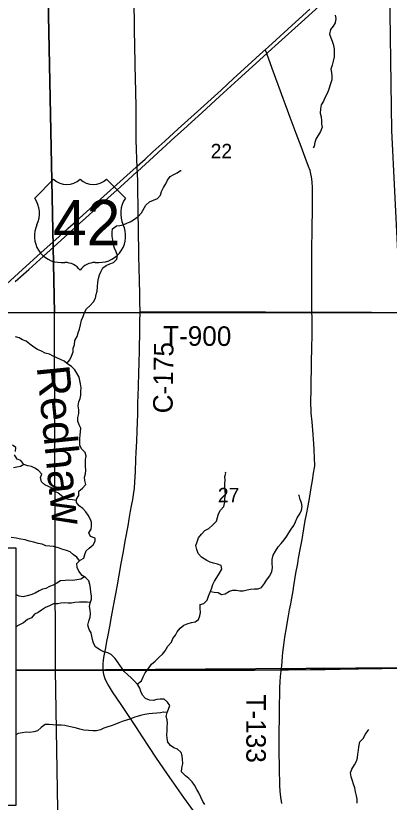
# Model space of a CAD drawing. Extents: x 0 to 34, y 0 to 22.
# Drawn here: x 5.987 to 7.072, y 17.462 to 19.744 of the extents above; entities that cross this region are included whole.
import ezdxf

# ---------------------------------------------------------------- set-up
doc = ezdxf.new("R2010")
doc.units = 0
for name, color, linetype in [('Default', 7, 'Continuous'), ('GM_X_County_Road', 7, 'Continuous'), ('GM_X_County_Road_Text', 7, 'Continuous'), ('GM_X_Minor_River', 7, 'Continuous'), ('GM_X_Minor_River_Text', 7, 'Continuous'), ('GM_X_Section', 7, 'Continuous'), ('GM_X_Section_Text', 7, 'Continuous'), ('GM_X_State_Route', 7, 'Continuous'), ('GM_X_Township_Road', 7, 'Continuous'), ('GM_X_Township_Road_Text', 7, 'Continuous'), ('GM_X_US_Location', 7, 'Continuous'), ('GM_X_US_Route', 7, 'Continuous'), ('GM_X_US_Shield', 7, 'Continuous'), ('SH_Text', 7, 'Continuous')]:
    doc.layers.add(name, color=color, linetype=linetype)

msp = doc.modelspace()

# ---------------------------------------------------------------- linework, layer by layer
at = {"layer": 'Default'}
msp.add_lwpolyline([(4.0336, 18.2003), (5.9872, 18.2003), (5.9872, 17.4527), (4.0336, 17.4527)], close=True, dxfattribs=at)
at = {"layer": 'GM_X_County_Road'}
for points in [[(6.3403, 19.2924), (6.3401, 19.2991), (6.3397, 19.3075), (6.339, 19.3239), (6.3378, 19.3605), (6.3372, 19.3796), (6.3366, 19.4139), (6.3365, 19.4358), (6.3365, 19.4792), (6.3359, 19.5239), (6.334, 19.5995), (6.3332, 19.6622), (6.3324, 19.6969), (6.3318, 19.7398), (6.3303, 19.7815), (6.3297, 19.8065), (6.329, 19.8322), (6.3289, 19.8539), (6.329, 19.8744), (6.3288, 19.8879)], [(6.348, 18.8852), (6.348, 18.8893), (6.3479, 18.911), (6.3473, 18.942), (6.3468, 18.97), (6.3454, 19.0181), (6.3447, 19.0397), (6.3443, 19.0643), (6.3438, 19.1129), (6.3435, 19.1375), (6.343, 19.162), (6.3426, 19.1774), (6.3426, 19.1936), (6.3418, 19.2339), (6.3413, 19.2587), (6.3403, 19.2924)], [(6.2412, 17.8453), (6.2408, 17.8488), (6.2405, 17.8547), (6.2409, 17.8638), (6.2418, 17.873), (6.2432, 17.8822), (6.2484, 17.9097), (6.252, 17.928), (6.2554, 17.9463), (6.261, 17.9769), (6.2633, 17.9891), (6.2672, 18.0109), (6.2728, 18.0413), (6.2814, 18.087), (6.2876, 18.121), (6.2937, 18.1548), (6.2992, 18.1844), (6.3061, 18.2242), (6.3132, 18.2642), (6.3166, 18.2834), (6.3206, 18.307), (6.3236, 18.3223), (6.3268, 18.3406), (6.3303, 18.3611), (6.3318, 18.3733), (6.3332, 18.3918), (6.3345, 18.4206), (6.336, 18.4578), (6.3366, 18.4766), (6.3383, 18.51), (6.3397, 18.5389), (6.3405, 18.5653), (6.3412, 18.5883), (6.342, 18.6192), (6.3426, 18.6444), (6.3433, 18.6658), (6.3439, 18.6818), (6.3443, 18.6953), (6.3449, 18.7099), (6.3457, 18.734), (6.346, 18.7464), (6.3463, 18.7619), (6.3465, 18.7836), (6.3473, 18.8209), (6.3478, 18.8551), (6.348, 18.8852)], [(6.5035, 17.4366), (6.4752, 17.4757), (6.4343, 17.5338), (6.4169, 17.5594), (6.3942, 17.5932), (6.3757, 17.621), (6.3555, 17.6516), (6.3381, 17.6784), (6.3143, 17.7137), (6.2932, 17.7455), (6.2684, 17.7826), (6.2592, 17.7972), (6.2545, 17.8048), (6.25, 17.8133), (6.2472, 17.8199), (6.2449, 17.8263), (6.2432, 17.8322), (6.2419, 17.8385), (6.2412, 17.8453)]]:
    msp.add_lwpolyline(points, dxfattribs=at)
at = {"layer": 'GM_X_Minor_River'}
for points in [[(6.9151, 19.7459), (6.9169, 19.7357), (6.9149, 19.7239), (6.9095, 19.7141), (6.9015, 19.7043), (6.8991, 19.6903), (6.9021, 19.6804), (6.9061, 19.6702), (6.9102, 19.6591), (6.9124, 19.6458), (6.9123, 19.6344), (6.9126, 19.6249), (6.9094, 19.6125), (6.9059, 19.6007), (6.9028, 19.5894), (6.9046, 19.5799), (6.9053, 19.5685), (6.9052, 19.5579), (6.9009, 19.5435), (6.897, 19.531), (6.8924, 19.5201), (6.8854, 19.5061), (6.8816, 19.4963), (6.8746, 19.4857), (6.8727, 19.4743), (6.8718, 19.4611), (6.874, 19.4508), (6.8754, 19.4394), (6.8753, 19.4299), (6.8771, 19.4204), (6.8721, 19.4083), (6.8667, 19.3985), (6.8598, 19.3876), (6.8559, 19.3759), (6.8536, 19.366), (6.8512, 19.3604)], [(6.1355, 18.7351), (6.1443, 18.7458), (6.149, 18.7568), (6.1536, 18.7685), (6.1541, 18.7791), (6.1572, 18.7897), (6.1588, 18.8014), (6.165, 18.8135), (6.1681, 18.8241), (6.172, 18.8347), (6.1751, 18.8472), (6.1782, 18.8604), (6.1825, 18.8714), (6.1864, 18.8831), (6.1922, 18.8933), (6.2017, 18.9027), (6.2124, 18.9144), (6.2185, 18.9242), (6.2209, 18.9355), (6.2233, 18.9454), (6.2249, 18.9571), (6.2258, 18.9715), (6.2277, 18.9817), (6.2305, 18.992), (6.2351, 19.0025), (6.2401, 19.0124), (6.25, 19.0195), (6.2607, 19.0243), (6.2706, 19.0284), (6.2805, 19.0381), (6.2825, 19.0487), (6.2784, 19.0594), (6.2739, 19.0693), (6.2703, 19.0819), (6.2688, 19.0929), (6.2674, 19.105), (6.2671, 19.116), (6.268, 19.1255), (6.2794, 19.1345), (6.2896, 19.1355), (6.2995, 19.1377), (6.3094, 19.1418), (6.3197, 19.1466), (6.3295, 19.1522), (6.3425, 19.162), (6.3521, 19.1721), (6.3651, 19.1948), (6.3758, 19.2041), (6.3868, 19.209), (6.3986, 19.2142), (6.4078, 19.2239), (6.4109, 19.2338), (6.4159, 19.2459), (6.4228, 19.2568), (6.4282, 19.267), (6.4355, 19.2775), (6.4462, 19.2831), (6.4564, 19.2883), (6.4659, 19.2947), (6.4675, 19.2947)], [(6.2541, 17.8956), (6.2431, 17.8988), (6.2311, 17.9046), (6.219, 17.9134), (6.2127, 17.9233), (6.2097, 17.9344), (6.2079, 17.9439), (6.2061, 17.9537), (6.2001, 17.9633), (6.1968, 17.9762), (6.1992, 17.9876), (6.2027, 17.9986), (6.2039, 18.0095), (6.2033, 18.019), (6.2015, 18.0301), (6.2034, 18.0399), (6.2066, 18.0509), (6.2067, 18.0607), (6.2052, 18.0718), (6.2042, 18.0828), (6.202, 18.0934), (6.1991, 18.1044), (6.1897, 18.114), (6.1795, 18.1202), (6.1698, 18.1324), (6.1653, 18.1431), (6.1647, 18.1545), (6.1742, 18.1646), (6.1845, 18.1699), (6.188, 18.1804), (6.1911, 18.191), (6.2006, 18.1989), (6.2117, 18.2087), (6.2178, 18.2192), (6.2172, 18.2287), (6.2043, 18.2326), (6.1995, 18.2441), (6.2056, 18.2543), (6.2072, 18.2645), (6.207, 18.2744), (6.2033, 18.2846), (6.1969, 18.2949), (6.1905, 18.3045), (6.1819, 18.3141), (6.1714, 18.3218), (6.1639, 18.3313), (6.1632, 18.3412), (6.1705, 18.3517), (6.1706, 18.3643), (6.1809, 18.3729), (6.1901, 18.3838), (6.1879, 18.3956), (6.1869, 18.4051), (6.19, 18.4153), (6.1904, 18.4251), (6.1898, 18.4365), (6.1899, 18.4464), (6.1892, 18.4563), (6.1915, 18.4665), (6.1886, 18.4764), (6.1792, 18.4867), (6.1733, 18.4974), (6.1734, 18.5179), (6.1739, 18.5274), (6.1747, 18.538), (6.1756, 18.5475), (6.1715, 18.557), (6.1674, 18.5676), (6.1671, 18.5787), (6.1706, 18.59), (6.1703, 18.6002), (6.1678, 18.612), (6.1705, 18.6234), (6.174, 18.6336), (6.176, 18.6434), (6.1765, 18.6544), (6.1766, 18.6643), (6.1752, 18.6765), (6.1733, 18.686), (6.1712, 18.6955), (6.1644, 18.7069), (6.1588, 18.7168), (6.1491, 18.726), (6.1378, 18.7334), (6.1272, 18.7414), (6.1174, 18.7465), (6.1065, 18.7511), (6.0959, 18.7561), (6.085, 18.7619), (6.0725, 18.7655), (6.0616, 18.7705), (6.0499, 18.7759), (6.0397, 18.7825), (6.0277, 18.791), (6.0176, 18.8002), (6.0066, 18.8041), (5.9964, 18.8099), (5.9858, 18.8122)], [(5.9857, 18.4795), (5.9873, 18.4909), (5.9771, 18.4978)], [(6.1635, 18.3373), (6.1522, 18.339), (6.1409, 18.3403), (6.1307, 18.3434), (6.1194, 18.3515), (6.1096, 18.3595), (6.0998, 18.3634), (6.0923, 18.373), (6.0821, 18.3784), (6.0719, 18.3827), (6.0622, 18.3915), (6.0592, 18.404), (6.0627, 18.4139), (6.053, 18.4242), (6.0428, 18.4315), (6.033, 18.4362), (6.0224, 18.4378), (6.0107, 18.4417), (6.0013, 18.4535), (5.9908, 18.4574), (5.9829, 18.4697)], [(6.0107, 18.4417), (6.0004, 18.4361), (5.9902, 18.4343), (5.9807, 18.4321)], [(6.34, 17.8042), (6.3519, 17.8146), (6.3573, 17.8255), (6.363, 17.8373), (6.3722, 17.8504), (6.3818, 17.8625), (6.3921, 17.8711), (6.4032, 17.8828), (6.4135, 17.8914), (6.4211, 17.9016), (6.4292, 17.9144), (6.4391, 17.9264), (6.4434, 17.937), (6.4507, 17.9468), (6.4564, 17.9566), (6.4649, 17.9675), (6.4755, 17.9762), (6.485, 17.9799), (6.4976, 17.9835), (6.5078, 17.9853), (6.5177, 17.9925), (6.5216, 18.0027), (6.5239, 18.0125), (6.5225, 18.0243), (6.523, 18.0353), (6.5333, 18.039), (6.5432, 18.048), (6.5471, 18.0601), (6.5556, 18.0813), (6.5598, 18.0934), (6.5641, 18.1036), (6.571, 18.1141), (6.5791, 18.1262), (6.5856, 18.1379), (6.5834, 18.1485), (6.5732, 18.1524), (6.5619, 18.1559), (6.5521, 18.1583), (6.5423, 18.1633), (6.5264, 18.1734), (6.5167, 18.1837), (6.513, 18.1951), (6.5104, 18.2065), (6.5139, 18.2175), (6.5182, 18.2296), (6.5262, 18.2394), (6.5366, 18.2507), (6.5484, 18.2562), (6.559, 18.266), (6.5705, 18.278), (6.5732, 18.2882), (6.576, 18.2988), (6.5818, 18.3094), (6.5917, 18.3203), (6.5941, 18.3324), (6.5942, 18.3438), (6.5965, 18.3537), (6.5959, 18.3658), (6.5948, 18.3757), (6.5949, 18.3863), (6.5954, 18.3965), (6.5947, 18.4068), (6.5974, 18.4166), (6.5963, 18.4193)], [(6.5526, 18.0739), (6.5634, 18.0717), (6.5748, 18.0704), (6.5846, 18.0647), (6.5956, 18.0664), (6.6082, 18.0743), (6.618, 18.0776), (6.6279, 18.0775), (6.6381, 18.0759), (6.6479, 18.0754), (6.6589, 18.0784), (6.6692, 18.0805), (6.6798, 18.0808), (6.6911, 18.0815), (6.7006, 18.0852), (6.7098, 18.0964), (6.7156, 18.1063), (6.7255, 18.1191), (6.7306, 18.1312), (6.7329, 18.1421), (6.7319, 18.1554), (6.732, 18.166), (6.7351, 18.1785), (6.7413, 18.1906), (6.7497, 18.2027), (6.7585, 18.2128), (6.7666, 18.223), (6.7742, 18.2339), (6.7807, 18.2437), (6.7877, 18.2543), (6.7949, 18.2652), (6.7996, 18.2754), (6.8042, 18.2871), (6.8123, 18.2984), (6.8173, 18.309), (6.8193, 18.3204), (6.8171, 18.331), (6.8138, 18.3409), (6.8101, 18.3523), (6.809, 18.3543)], [(6.1723, 18.1626), (6.1648, 18.1731), (6.155, 18.18), (6.1449, 18.1881), (6.1343, 18.1923), (6.1211, 18.1963), (6.1109, 18.1998), (6.0969, 18.2045), (6.0863, 18.2053), (6.0742, 18.2062), (6.0637, 18.2105), (6.0516, 18.2129), (6.0391, 18.2168), (6.0262, 18.22), (6.0145, 18.2235), (6.0017, 18.2255), (5.9877, 18.2287), (5.9737, 18.2303)], [(6.1866, 18.1159), (6.1764, 18.1092), (6.1646, 18.1071), (6.1529, 18.1057), (6.1412, 18.1062), (6.1305, 18.1055), (6.1173, 18.1049), (6.1066, 18.0981), (6.0956, 18.0918), (6.0853, 18.0881), (6.0747, 18.0821), (6.0648, 18.08), (6.0549, 18.0751), (6.0431, 18.0688), (6.031, 18.064), (6.02, 18.0607), (6.0082, 18.0581), (5.9972, 18.0601), (5.9868, 18.0646)], [(6.2039, 18.0415), (6.194, 18.043), (6.1815, 18.0428), (6.1717, 18.0425), (6.1588, 18.0411), (6.1493, 18.0393), (6.1395, 18.0398), (6.1296, 18.041), (6.1182, 18.0392), (6.1088, 18.0374), (6.097, 18.0379), (6.0852, 18.0319), (6.0731, 18.0275), (6.062, 18.0197), (6.0518, 18.0129), (6.0415, 18.0073), (6.0331, 17.9972), (6.0213, 17.9924), (6.0091, 17.9826), (5.9961, 17.9755), (5.9868, 17.9708)], [(6.5362, 17.455), (6.531, 17.4645), (6.5251, 17.4763), (6.5191, 17.4889), (6.5131, 17.4988), (6.5061, 17.5114), (6.4993, 17.521), (6.4903, 17.5306), (6.4798, 17.5386), (6.4685, 17.5505), (6.4694, 17.5607), (6.4729, 17.574), (6.4715, 17.5861), (6.4708, 17.5968), (6.4675, 17.6063), (6.457, 17.6159), (6.4464, 17.6194), (6.4362, 17.6263), (6.4284, 17.6367), (6.4273, 17.6465), (6.4259, 17.6583), (6.4271, 17.6685), (6.4272, 17.6811), (6.4281, 17.6905), (6.4266, 17.7008), (6.4237, 17.7107), (6.4268, 17.7224), (6.4311, 17.7322), (6.4346, 17.7428), (6.4282, 17.7524), (6.4181, 17.7612), (6.4063, 17.7609), (6.3968, 17.7599), (6.3866, 17.757), (6.3752, 17.7582), (6.3643, 17.7633), (6.3549, 17.7728), (6.3508, 17.7831), (6.3471, 17.7926), (6.3415, 17.8026), (6.3318, 17.8129), (6.3224, 17.8225), (6.3122, 17.8313), (6.3017, 17.8409), (6.2961, 17.8504), (6.2898, 17.86), (6.2827, 17.8695), (6.2759, 17.8791), (6.2639, 17.8902), (6.2541, 17.8956)], [(6.4268, 17.7224), (6.4166, 17.7229), (6.4071, 17.7211), (6.3965, 17.7201), (6.3844, 17.7198), (6.3741, 17.7184), (6.3624, 17.717), (6.3529, 17.7144), (6.3423, 17.7119), (6.3301, 17.7082), (6.318, 17.7034), (6.3085, 17.7), (6.2963, 17.696), (6.2865, 17.6927), (6.2751, 17.6879), (6.2637, 17.6834), (6.2542, 17.6805), (6.2432, 17.6772), (6.2329, 17.6719), (6.2219, 17.669), (6.2105, 17.6695), (6.198, 17.67), (6.1852, 17.6713), (6.1735, 17.6737), (6.1633, 17.6768), (6.1508, 17.6803), (6.141, 17.6816), (6.1296, 17.6843), (6.119, 17.6852), (6.1077, 17.6861), (6.0948, 17.6866), (6.0842, 17.6874), (6.0721, 17.6879), (6.0607, 17.6793), (6.0503, 17.6695), (6.039, 17.6659), (6.0272, 17.6648), (6.0174, 17.6653), (6.0064, 17.6631), (5.9942, 17.6614), (5.9868, 17.6573)], [(6.9786, 17.4594), (6.979, 17.4712), (6.9768, 17.4807), (6.9743, 17.4921), (6.9725, 17.5035), (6.9684, 17.5141), (6.9659, 17.5237), (6.9618, 17.5355), (6.9596, 17.5472), (6.9631, 17.5582), (6.9708, 17.5707), (6.9766, 17.5812), (6.9801, 17.5911), (6.9813, 17.6017), (6.9825, 17.6127), (6.9841, 17.6229), (6.9869, 17.6369), (6.9961, 17.6467), (7.003, 17.6591), (7.0103, 17.6689), (7.0133, 17.6735)]]:
    msp.add_lwpolyline(points, dxfattribs=at)
at = {"layer": 'GM_X_Section'}
for points in [[(6.0796, 19.8902), (6.0998, 18.8817), (5.0689, 18.882), (5.0715, 19.8844)], [(7.0719, 19.8884), (7.0785, 19.4112), (7.105, 18.883), (6.0998, 18.8817), (6.0796, 19.8902)], [(5.9868, 17.8455), (6.1027, 17.8448), (6.0998, 18.8817), (5.0689, 18.882), (5.0723, 18.2003), (5.9868, 18.2003)], [(7.105, 18.883), (7.1203, 17.8521), (6.1027, 17.8448), (6.0998, 18.8817)], [(7.1203, 17.8521), (7.1264, 16.8648), (6.1739, 16.8615), (6.1193, 16.8628), (6.1027, 17.8448)], [(5.0909, 17.4527), (5.1149, 16.8654), (5.1862, 16.8638), (6.1193, 16.8628), (6.1027, 17.8448), (5.9868, 17.8455), (5.9868, 17.4527)]]:
    msp.add_lwpolyline(points, close=True, dxfattribs=at)
at = {"layer": 'GM_X_State_Route'}
msp.add_lwpolyline([(5.9868, 17.8453), (6.0453, 17.8454), (6.0939, 17.8456), (6.1467, 17.8456), (6.184, 17.8456), (6.2253, 17.8451), (6.2412, 17.8453), (6.2938, 17.8454), (6.36, 17.8451), (6.4041, 17.8451), (6.4481, 17.845), (6.5009, 17.8451), (6.5599, 17.8453), (6.6064, 17.8451), (6.6437, 17.8451), (6.681, 17.8451), (6.7585, 17.8461), (6.7797, 17.8464), (6.8437, 17.8468), (6.8863, 17.8473), (6.9292, 17.8483), (6.9833, 17.8491), (7.0515, 17.8505), (7.1089, 17.8514)], dxfattribs=at)
at = {"layer": 'GM_X_Township_Road'}
for points in [[(6.7166, 19.6345), (6.7138, 19.642), (6.7124, 19.6458)], [(6.7499, 19.5436), (6.7324, 19.5915), (6.7166, 19.6345)], [(6.8475, 18.8842), (6.8475, 18.8853), (6.8472, 18.907), (6.8473, 18.9256), (6.8471, 18.9536), (6.847, 18.9784), (6.8472, 19.0032), (6.847, 19.0156), (6.8471, 19.0342), (6.8474, 19.0559), (6.8487, 19.1336), (6.8491, 19.1771), (6.8492, 19.2113), (6.8488, 19.2455), (6.8482, 19.261), (6.8473, 19.2704), (6.8464, 19.2766), (6.8444, 19.2857), (6.842, 19.2948), (6.8378, 19.3066), (6.8283, 19.3327), (6.8164, 19.3645), (6.8019, 19.4025), (6.7845, 19.4486), (6.7728, 19.481), (6.7643, 19.504), (6.7526, 19.5361), (6.7499, 19.5436)], [(6.348, 18.8852), (6.3522, 18.8852), (6.3677, 18.885), (6.3926, 18.8851), (6.4454, 18.8853), (6.4703, 18.8854), (6.5014, 18.8851), (6.5449, 18.8849), (6.576, 18.8848), (6.6662, 18.8847), (6.7128, 18.8845), (6.7626, 18.8844), (6.803, 18.8842), (6.8465, 18.8842), (6.8475, 18.8842)], [(6.7585, 17.8461), (6.7598, 17.8573), (6.7622, 17.8847), (6.7634, 17.8965), (6.7651, 17.9112), (6.7669, 17.9252), (6.769, 17.9405), (6.7734, 17.968), (6.7764, 17.9865), (6.7795, 18.0026), (6.7828, 18.0201), (6.7862, 18.0381), (6.789, 18.0537), (6.7926, 18.075), (6.7951, 18.0903), (6.8012, 18.1264), (6.8063, 18.1543), (6.809, 18.1701), (6.8143, 18.2003), (6.8188, 18.2244), (6.8241, 18.255), (6.8283, 18.2794), (6.8317, 18.2965), (6.8364, 18.3222), (6.8404, 18.3438), (6.8455, 18.3739), (6.8491, 18.3956), (6.8526, 18.4165), (6.8549, 18.432), (6.8557, 18.4392), (6.8555, 18.4605), (6.8543, 18.4857), (6.8535, 18.5022), (6.8511, 18.5287), (6.8478, 18.5658), (6.8456, 18.5906), (6.8449, 18.6029), (6.8448, 18.6153), (6.8457, 18.6681), (6.8466, 18.7329), (6.8476, 18.7863), (6.8483, 18.811), (6.848, 18.8699), (6.8475, 18.8842)], [(6.8475, 18.8842), (6.8838, 18.8841), (6.9211, 18.8841), (6.9709, 18.8841), (6.9989, 18.884), (7.0206, 18.8838), (7.0859, 18.8833)], [(6.7597, 17.4582), (6.7575, 17.4765), (6.7556, 17.4941), (6.7544, 17.5103), (6.7539, 17.5232), (6.7532, 17.5483), (6.7533, 17.5695), (6.7527, 17.6036), (6.7527, 17.6617), (6.7531, 17.7106), (6.7533, 17.7456), (6.7541, 17.7742), (6.7546, 17.795), (6.7555, 17.8115), (6.7567, 17.8268), (6.758, 17.8421), (6.7585, 17.8461)]]:
    msp.add_lwpolyline(points, dxfattribs=at)
at = {"layer": 'GM_X_US_Route'}
for points in [[(5.9852, 18.9729), (6.0248, 19.0079), (6.0569, 19.0373), (6.1286, 19.1017), (6.1493, 19.1204), (6.1724, 19.1413), (6.191, 19.1578), (6.2209, 19.185), (6.2719, 19.2306), (6.302, 19.2575), (6.3387, 19.291), (6.3403, 19.2924), (6.3757, 19.3243), (6.4491, 19.3915), (6.4744, 19.4145), (6.4976, 19.4352), (6.5273, 19.4626), (6.5803, 19.5105), (6.6331, 19.5587), (6.7166, 19.6345), (6.7206, 19.6381), (6.7505, 19.6653), (6.8174, 19.7258), (6.983, 19.8762)], [(5.9141, 18.9251), (5.9952, 18.9975), (6.0598, 19.0558), (6.113, 19.1035), (6.1383, 19.1265), (6.1613, 19.1474), (6.2239, 19.2034), (6.3095, 19.2802), (6.3371, 19.3052), (6.3397, 19.3075), (6.3625, 19.3281), (6.3855, 19.349), (6.4199, 19.3804), (6.4591, 19.4159), (6.5052, 19.4577), (6.5835, 19.5286), (6.6201, 19.5622), (6.6616, 19.5998), (6.6961, 19.6312), (6.7124, 19.6458), (6.7215, 19.654), (6.7998, 19.725), (6.8411, 19.7628)]]:
    msp.add_lwpolyline(points, dxfattribs=at)
at = {"layer": 'GM_X_US_Shield'}
for p, q in [((6.0969, 19.2699), (6.0419, 19.2149)), ((6.3056, 19.2149), (6.2507, 19.2699)), ((6.1188, 19.0282), (6.1298, 19.0282)), ((6.2177, 19.0282), (6.2287, 19.0282))]:
    msp.add_line(p, q, dxfattribs=at)
for centre, radius, start, end in [((6.1353, 19.3091), 0.0549, 225.573, 314.427), ((6.2122, 19.3091), 0.0549, 225.573, 314.427), ((5.9789, 19.1708), 0.0769, 334.5471, 35.0009), ((6.3686, 19.1708), 0.0769, 144.9991, 205.4529), ((6.118, 19.1051), 0.0769, 154.8319, 270.6383), ((6.2295, 19.1051), 0.0769, 269.3617, 25.1681), ((6.1298, 18.9732), 0.0549, 36.8699, 90), ((6.2177, 18.9732), 0.0549, 90, 143.1301)]:
    msp.add_arc(centre, radius, start, end, dxfattribs=at)
at = {"layer": 'SH_Text'}
msp.add_lwpolyline([(4.0336, 18.2003), (5.9868, 18.2003), (5.9868, 17.4527), (4.0336, 17.4527)], close=True, dxfattribs=at)

# ---------------------------------------------------------------- texts
at = {"layer": 'GM_X_County_Road_Text'}
msp.add_text('C-175', height=0.05682, rotation=89.1754, dxfattribs=at).set_placement((6.4425, 18.5901))
at = {"layer": 'GM_X_Minor_River_Text'}
msp.add_text('Redhaw', height=0.09473, rotation=275.7262, dxfattribs=at).set_placement((6.0477, 18.7252))
at = {"layer": 'GM_X_Section_Text'}
for s, p in [('22', (6.5533, 19.3305)), ('27', (6.5742, 18.3322))]:
    msp.add_text(s, height=0.04186, rotation=0, dxfattribs=at).set_placement(p)
at = {"layer": 'GM_X_Township_Road_Text'}
for s, rotation, p in [('T-900', 359.7177, (6.4148, 18.7869)), ('T-133', 270, (6.6568, 17.7747))]:
    msp.add_text(s, height=0.05682, rotation=rotation, dxfattribs=at).set_placement(p)
at = {"layer": 'GM_X_US_Location'}
for s in ['0', '/']:
    msp.add_text(s, height=0.000189, dxfattribs=at).set_placement((6.1737, 19.1425))
msp.add_text('42', height=0.000189, rotation=0, dxfattribs=at).set_placement((6.1346, 19.1033))
at = {"layer": 'GM_X_US_Shield'}
msp.add_text('42', height=0.13184, dxfattribs=at).set_placement((6.095, 19.0776))

doc.saveas('drawing.dxf')
